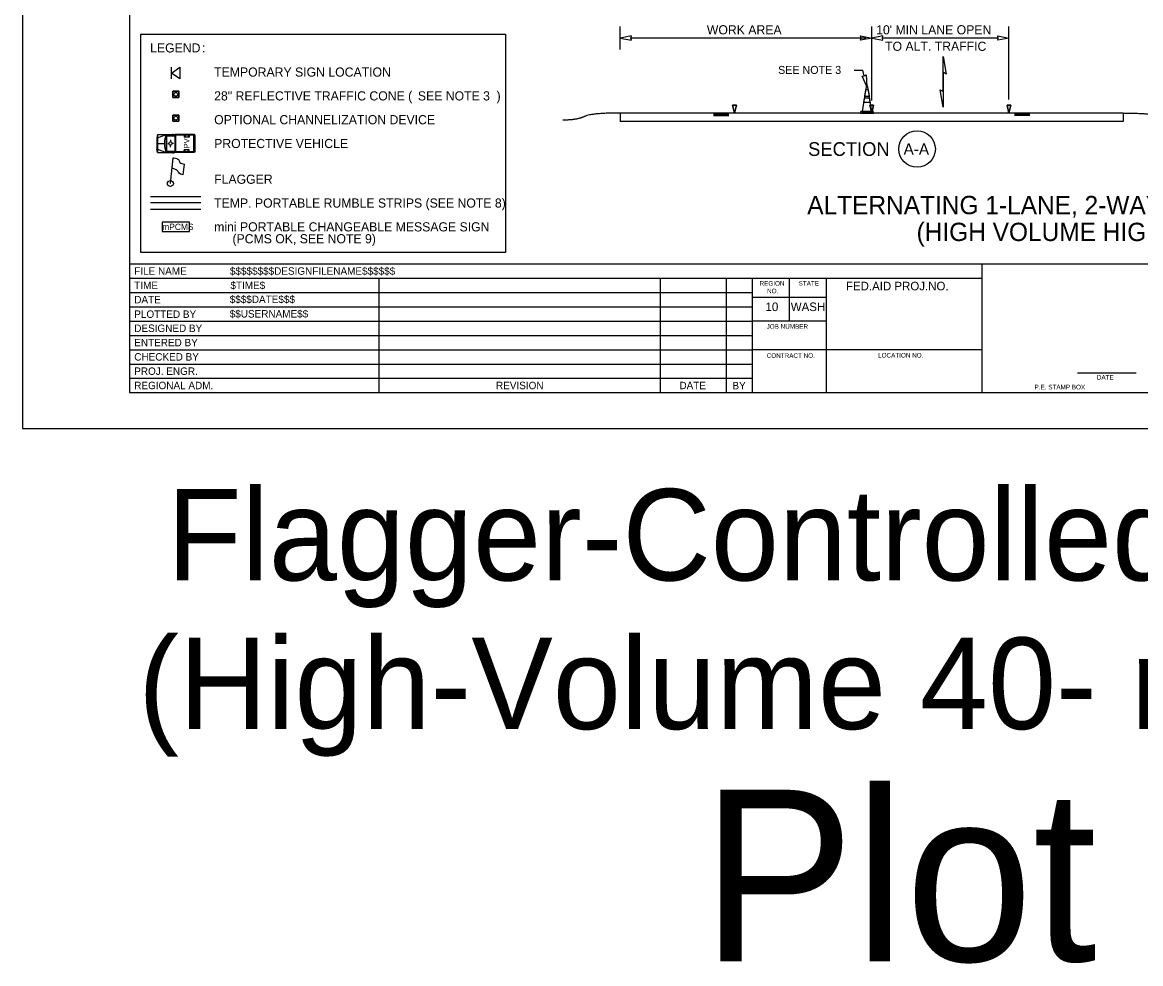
# Model space of a CAD drawing. Extents: x 99999.1 to 100095.7, y 99995 to 100010.7.
# Drawn here: x 100039.06 to 100048.84, y 99995.01 to 100003.24 of the extents above; entities that cross this region are included whole.
import ezdxf

# ---------------------------------------------------------------- set-up
doc = ezdxf.new("R2010")
doc.units = 0
for name, color, linetype in [('SH_DE_DetailHeading1Text', 7, 'Continuous'), ('SH_GI_PlotLimits', 7, 'Continuous'), ('SH_GI_SheetBorder', 7, 'Continuous'), ('SH_GI_SheetLocationText', 7, 'Continuous'), ('SH_GI_SheetTextInCells', 7, 'Continuous'), ('SH_GI_TitleBlockText', 7, 'Continuous'), ('TR_WZ_FlaggingStation', 7, 'Continuous'), ('TR_WZ_PCMS', 7, 'Continuous'), ('TR_WZ_PortableSignMountBlk-Org', 7, 'Continuous'), ('TR_WZ_ProtectiveVehicle', 7, 'Continuous'), ('TR_WZ_TrafficCone', 7, 'Continuous'), ('TR_WZ_TrafficConeElev', 7, 'Continuous'), ('TR_WZ_WorkZoneDetails', 7, 'Continuous'), ('TR_WZ_WorkZoneTextCurrent', 7, 'Continuous')]:
    doc.layers.add(name, color=color, linetype=linetype)

msp = doc.modelspace()

# ---------------------------------------------------------------- linework, layer by layer
at = {"layer": 'SH_GI_PlotLimits'}
msp.add_lwpolyline([(100039.0625, 99999.6875), (100056.0625, 99999.6875), (100056.0625, 100010.6875), (100039.0625, 100010.6875)], close=True, dxfattribs=at)
at = {"layer": 'SH_GI_SheetBorder'}
for p, q in [((100040, 100010.375), (100040, 100000)), ((100040, 100001.1259), (100055.75, 100001.1259)), ((100047.4566, 100000), (100047.4566, 100001.1259)), ((100040, 100001.0008), (100047.4566, 100001.0008)), ((100042.179, 100001.0008), (100042.179, 100000)), ((100044.641, 100001.0008), (100044.641, 100000)), ((100045.2164, 100001.0008), (100045.2164, 100000)), ((100045.4451, 100001.0008), (100045.4451, 100000)), ((100045.7719, 100000.6255), (100045.7719, 100001.0008)), ((100046.0956, 100000), (100046.0956, 100001.0008)), ((100040, 100000.8757), (100042.1821, 100000.8757)), ((100042.1821, 100000.8757), (100045.4466, 100000.8757)), ((100046.0958, 100000.831), (100045.4466, 100000.831)), ((100040, 100000.7506), (100042.1821, 100000.7506)), ((100042.1821, 100000.7506), (100045.4466, 100000.7506)), ((100040, 100000.6255), (100045.4466, 100000.6255)), ((100046.0958, 100000.6255), (100045.4466, 100000.6255)), ((100040, 100000.5004), (100045.4466, 100000.5004)), ((100040, 100000.3753), (100045.4466, 100000.3753)), ((100047.4566, 100000.3753), (100045.4466, 100000.3753)), ((100040, 100000.2502), (100045.4466, 100000.2502)), ((100040, 100000.1251), (100045.4466, 100000.1251)), ((100048.2903, 100000.1733), (100048.802, 100000.1733)), ((100040, 100000), (100055.75, 100000))]:
    msp.add_line(p, q, dxfattribs=at)
at = {"layer": 'TR_WZ_FlaggingStation'}
for p, q in [((100040.3571, 100001.8286), (100040.3828, 100002.0533)), ((100040.3723, 100001.9621), (100040.3828, 100002.0536)), ((100040.3723, 100001.9621), (100040.3723, 100001.9621)), ((100040.4771, 100001.9993), (100040.4665, 100001.9056))]:
    msp.add_line(p, q, dxfattribs=at)
for points in [[(100040.3828, 100002.0536), (100040.3874, 100002.0525), (100040.4016, 100002.0498), (100040.4127, 100002.0465), (100040.4204, 100002.0416), (100040.4273, 100002.0378), (100040.4318, 100002.0324), (100040.4352, 100002.0261), (100040.4356, 100002.0211), (100040.4399, 100002.0138), (100040.4486, 100002.0078), (100040.4585, 100002.0036), (100040.4771, 100001.9993)], [(100040.4665, 100001.9056), (100040.46, 100001.9067), (100040.4458, 100001.9104), (100040.4333, 100001.9188), (100040.4281, 100001.9273), (100040.425, 100001.9355), (100040.4177, 100001.9442), (100040.4089, 100001.9492), (100040.395, 100001.9548), (100040.3723, 100001.9621)]]:
    msp.add_lwpolyline(points, dxfattribs=at)
msp.add_circle((100040.3571, 100001.8286), 0.026, dxfattribs=at)
at = {"layer": 'TR_WZ_PCMS'}
msp.add_lwpolyline([(100040.2841, 100001.41), (100040.5241, 100001.41), (100040.5241, 100001.49), (100040.2841, 100001.49)], close=True, dxfattribs=at)
msp.add_lwpolyline([(100040.2841, 100001.41), (100040.5241, 100001.41), (100040.5241, 100001.49), (100040.2841, 100001.49), (100040.2841, 100001.41)], dxfattribs=at)
at = {"layer": 'TR_WZ_PortableSignMountBlk-Org'}
msp.add_line((100040.3682, 100002.7454), (100040.3682, 100002.8454), dxfattribs=at)
msp.add_lwpolyline([(100040.3682, 100002.7953), (100040.44, 100002.8454), (100040.44, 100002.7454)], close=True, dxfattribs=at)
at = {"layer": 'TR_WZ_ProtectiveVehicle'}
for p, q in [((100040.245, 100002.259), (100040.2376, 100002.2267)), ((100040.245, 100002.259), (100040.245, 100002.099)), ((100040.245, 100002.259), (100040.3962, 100002.259)), ((100040.245, 100002.2297), (100040.3206, 100002.259)), ((100040.3206, 100002.259), (100040.3206, 100002.099)), ((100040.322, 100002.259), (100040.322, 100002.099)), ((100040.322, 100002.259), (100040.3316, 100002.2466)), ((100040.322, 100002.2466), (100040.3962, 100002.2466)), ((100040.3756, 100002.2613), (100040.3846, 100002.2613)), ((100040.3962, 100002.259), (100040.3962, 100002.099)), ((100040.5629, 100002.259), (100040.3984, 100002.259)), ((100040.3984, 100002.259), (100040.3984, 100002.099)), ((100040.5583, 100002.2526), (100040.403, 100002.2526)), ((100040.403, 100002.2526), (100040.403, 100002.1054)), ((100040.4772, 100002.2526), (100040.4772, 100002.2342)), ((100040.4852, 100002.2526), (100040.4852, 100002.2342)), ((100040.5124, 100002.2526), (100040.5124, 100002.2342)), ((100040.5212, 100002.2526), (100040.5212, 100002.2342)), ((100040.5583, 100002.2526), (100040.5583, 100002.1054)), ((100040.5629, 100002.259), (100040.5629, 100002.099)), ((100040.5671, 100002.2564), (100040.5635, 100002.2564)), ((100040.5635, 100002.2564), (100040.5635, 100002.1017)), ((100040.5706, 100002.2515), (100040.5706, 100002.1065)), ((100040.2376, 100002.2267), (100040.2376, 100002.1313)), ((100040.245, 100002.179), (100040.3058, 100002.179)), ((100040.3341, 100002.1791), (100040.3442, 100002.1791)), ((100040.3582, 100002.2107), (100040.3582, 100002.1978)), ((100040.3588, 100002.1482), (100040.3586, 100002.1603)), ((100040.3695, 100002.1787), (100040.3695, 100002.1787)), ((100040.3829, 100002.1784), (100040.371, 100002.1787)), ((100040.5212, 100002.2342), (100040.4772, 100002.2342)), ((100040.5706, 100002.1903), (100040.5635, 100002.1873)), ((100040.5706, 100002.1678), (100040.5635, 100002.1708)), ((100040.5687, 100002.179), (100040.5654, 100002.179)), ((100040.5671, 100002.1813), (100040.5671, 100002.1768)), ((100040.245, 100002.099), (100040.2376, 100002.1313)), ((100040.245, 100002.1283), (100040.3206, 100002.099)), ((100040.245, 100002.099), (100040.3962, 100002.099)), ((100040.322, 100002.1114), (100040.3962, 100002.1114)), ((100040.3299, 100002.1114), (100040.322, 100002.099)), ((100040.3756, 100002.0968), (100040.3846, 100002.0968)), ((100040.5629, 100002.099), (100040.3984, 100002.099)), ((100040.5583, 100002.1054), (100040.403, 100002.1054)), ((100040.4772, 100002.1054), (100040.4772, 100002.1238)), ((100040.5212, 100002.1238), (100040.4772, 100002.1238)), ((100040.4852, 100002.1054), (100040.4852, 100002.1238)), ((100040.5124, 100002.1054), (100040.5124, 100002.1238)), ((100040.5212, 100002.1054), (100040.5212, 100002.1238)), ((100040.5671, 100002.1017), (100040.5635, 100002.1017))]:
    msp.add_line(p, q, dxfattribs=at)
for centre, major_axis, start_param, end_param in [((100040.4286, 100002.179), (0, -0.1679), 4.215667, 5.208926), ((100040.5671, 100002.2515), (0, 0.00488), 4.712389, 6.283185), ((100040.5671, 100002.1065), (0, -0.00488), 0, 1.570796)]:
    msp.add_ellipse(centre, major_axis=major_axis, ratio=0.73155, start_param=start_param, end_param=end_param, dxfattribs=at)
for centre, major_axis in [((100040.3582, 100002.179), (0, 0.0154)), ((100040.5671, 100002.179), (0, 0.00225))]:
    msp.add_ellipse(centre, major_axis=major_axis, ratio=0.73155, dxfattribs=at)
at = {"layer": 'TR_WZ_TrafficCone'}
for points in [[(100040.3775, 100002.6355), (100040.4308, 100002.6355), (100040.4308, 100002.5821), (100040.3775, 100002.5821), (100040.3775, 100002.6355)], [(100040.3775, 100002.5821), (100040.4308, 100002.5821), (100040.4308, 100002.6355), (100040.3775, 100002.6355), (100040.3775, 100002.5821)], [(100040.3775, 100002.4272), (100040.4308, 100002.4272), (100040.4308, 100002.3739), (100040.3775, 100002.3739), (100040.3775, 100002.4272)], [(100040.3775, 100002.3739), (100040.4308, 100002.3739), (100040.4308, 100002.4272), (100040.3775, 100002.4272), (100040.3775, 100002.3739)]]:
    msp.add_lwpolyline(points, dxfattribs=at)
for centre in [(100040.4041, 100002.6088), (100040.4041, 100002.4005)]:
    msp.add_circle(centre, 0.0167, dxfattribs=at)
at = {"layer": 'TR_WZ_TrafficConeElev'}
for p, q in [((100046.4363, 100002.6476), (100046.428, 100002.5934)), ((100046.4616, 100002.6476), (100046.4363, 100002.6476)), ((100046.4699, 100002.5934), (100046.4616, 100002.6476)), ((100046.4255, 100002.5768), (100046.4197, 100002.5393)), ((100046.4197, 100002.5393), (100046.4782, 100002.5393)), ((100046.4724, 100002.5768), (100046.4255, 100002.5768)), ((100046.428, 100002.5934), (100046.4699, 100002.5934)), ((100046.4782, 100002.5393), (100046.4724, 100002.5768)), ((100046.3953, 100002.458), (100046.3911, 100002.4538)), ((100046.3911, 100002.4538), (100046.3911, 100002.4455)), ((100046.3911, 100002.4455), (100046.5068, 100002.4455)), ((100046.4073, 100002.458), (100046.3953, 100002.458)), ((100046.5068, 100002.4538), (100046.5026, 100002.458)), ((100046.5068, 100002.4455), (100046.5068, 100002.4538))]:
    msp.add_line(p, q, dxfattribs=at)
msp.add_lwpolyline([(100046.4073, 100002.458), (100046.4906, 100002.458), (100046.4568, 100002.6788), (100046.4411, 100002.6788)], close=True, dxfattribs=at)
msp.add_lwpolyline([(100046.4073, 100002.458), (100046.4906, 100002.458), (100046.4568, 100002.6788), (100046.4411, 100002.6788)], close=True, dxfattribs=at)
msp.add_lwpolyline([(100046.5026, 100002.458), (100046.4906, 100002.458), (100046.4073, 100002.458)], dxfattribs=at)
at = {"layer": 'TR_WZ_WorkZoneDetails'}
for p, q in [((100044.2907, 100003.0015), (100044.2907, 100003.2015)), ((100046.4907, 100002.5552), (100046.4907, 100003.2015)), ((100047.6907, 100002.5652), (100047.6907, 100003.2015)), ((100046.4387, 100003.1015), (100044.3844, 100003.1015)), ((100047.597, 100003.1015), (100046.5844, 100003.1015)), ((100046.3358, 100002.8215), (100046.412, 100002.8215)), ((100046.4255, 100002.7696), (100046.412, 100002.8215)), ((100047.1157, 100002.8019), (100047.1157, 100002.6331)), ((100047.1157, 100002.6331), (100047.1157, 100002.8019)), ((100044.2907, 100002.4454), (100044.2907, 100002.3704)), ((100048.6907, 100002.4454), (100044.2907, 100002.4454)), ((100045.1077, 100002.4402), (100045.2407, 100002.4402)), ((100047.8737, 100002.4398), (100047.7407, 100002.4398)), ((100048.6907, 100002.4454), (100048.6907, 100002.3704)), ((100048.6907, 100002.3704), (100044.2907, 100002.3704)), ((100045.1077, 100002.4346), (100045.2407, 100002.4346)), ((100045.1077, 100002.4289), (100045.2407, 100002.4289)), ((100045.1077, 100002.4237), (100045.2407, 100002.4237)), ((100047.8737, 100002.4342), (100047.7407, 100002.4342)), ((100047.8737, 100002.4285), (100047.7407, 100002.4285)), ((100047.8737, 100002.4233), (100047.7407, 100002.4233)), ((100040.6241, 100001.7135), (100040.1841, 100001.7135)), ((100040.6241, 100001.6587), (100040.1841, 100001.6587)), ((100040.6241, 100001.603), (100040.1841, 100001.603))]:
    msp.add_line(p, q, dxfattribs=at)
for points in [[(100044.2907, 100003.1015), (100044.389, 100003.0822), (100044.3844, 100003.1015), (100044.389, 100003.1208)], [(100046.4907, 100003.1015), (100046.3924, 100003.0822), (100046.397, 100003.1015), (100046.3924, 100003.1208)], [(100046.4907, 100003.1015), (100046.589, 100003.0822), (100046.5844, 100003.1015), (100046.589, 100003.1208)], [(100047.6907, 100003.1015), (100047.5924, 100003.0822), (100047.597, 100003.1015), (100047.5924, 100003.1208)], [(100047.1157, 100002.9395), (100047.1427, 100002.7863), (100047.1157, 100002.8019)], [(100046.449, 100002.6788), (100046.4057, 100002.7692), (100046.4255, 100002.7696), (100046.443, 100002.7788)], [(100047.1157, 100002.4954), (100047.0887, 100002.6487), (100047.1157, 100002.6331)], [(100045.2907, 100002.4454), (100045.274, 100002.5152), (100045.3073, 100002.5152)], [(100046.4907, 100002.4454), (100046.474, 100002.5152), (100046.5074, 100002.5152)], [(100047.6907, 100002.4454), (100047.674, 100002.5152), (100047.7073, 100002.5152)]]:
    msp.add_lwpolyline(points, close=True, dxfattribs=at)
for points in [[(100045.3073, 100002.5152), (100045.274, 100002.5152), (100045.2907, 100002.4454), (100045.3073, 100002.5152)], [(100046.5074, 100002.5152), (100046.474, 100002.5152), (100046.4907, 100002.4454), (100046.5074, 100002.5152)], [(100047.7073, 100002.5152), (100047.674, 100002.5152), (100047.6907, 100002.4454), (100047.7073, 100002.5152)]]:
    msp.add_lwpolyline(points, dxfattribs=at)
msp.add_circle((100046.8872, 100002.1305), 0.16, dxfattribs=at)
for points in [[(100044.2907, 100002.4454), (100044.0395, 100002.4454), (100043.914, 100002.3833), (100043.7886, 100002.3833)], [(100048.6907, 100002.4454), (100048.9419, 100002.4456), (100049.0674, 100002.3835), (100049.1928, 100002.3836)]]:
    msp.add_open_spline(points, degree=2, dxfattribs=at)
at = {"layer": 'TR_WZ_WorkZoneTextCurrent'}
msp.add_lwpolyline([(100040.1, 100003.1351), (100043.2886, 100003.1351), (100043.2886, 100001.2259), (100040.1, 100001.2259)], close=True, dxfattribs=at)

# ---------------------------------------------------------------- texts
at = {"layer": 'SH_DE_DetailHeading1Text'}
for s, p in [('ALTERNATING 1-LANE, 2-WAY TRAFFIC: FLAGGER-CONTROLLED', (100045.9266, 100001.5606)), ('(HIGH VOLUME HIGHWAYS, 40 MPH OR LESS)', (100046.8827, 100001.3259))]:
    msp.add_text(s, height=0.16, rotation=360, dxfattribs=at).set_placement(p)
at = {"layer": 'SH_GI_SheetLocationText'}
for s, height, p in [('Flagger-Controlled Alt Traffic+RS', 0.8, (100040.3275, 99998.3571)), ('(High-Volume 40- mph Highways)', 0.8, (100040.0757, 99997.0571)), ('Plot 3', 1.5, (100045.0008, 99995.0267))]:
    msp.add_text(s, height=height, dxfattribs=at).set_placement(p)
at = {"layer": 'SH_GI_SheetTextInCells'}
for s, height, p in [('FILE NAME', 0.06505, (100040.041, 100001.0308)), ('TIME', 0.06505, (100040.041, 100000.9057)), ('REGION', 0.04003, (100045.5099, 100000.9352)), ('STATE', 0.04003, (100045.8511, 100000.9357)), ('FED.AID PROJ.NO.', 0.07506, (100046.2652, 100000.8945)), ('NO.', 0.04003, (100045.5752, 100000.869)), ('DATE', 0.06505, (100040.041, 100000.7806)), ('10', 0.07506, (100045.5621, 100000.7131)), ('WASH', 0.07506, (100045.7826, 100000.7131)), ('PLOTTED BY', 0.06505, (100040.041, 100000.6538)), ('DESIGNED BY', 0.065052, (100040.041, 100000.5304)), ('JOB NUMBER', 0.04003, (100045.5712, 100000.5587)), ('ENTERED BY', 0.06505, (100040.041, 100000.4053)), ('CHECKED BY', 0.06505, (100040.041, 100000.2802)), ('CONTRACT NO.', 0.040032, (100045.5725, 100000.3037)), ('LOCATION NO.', 0.040032, (100046.5465, 100000.3067)), ('PROJ. ENGR.', 0.065052, (100040.041, 100000.1551)), ('REGIONAL ADM.', 0.065052, (100040.041, 100000.03)), ('REVISION', 0.06505, (100043.2048, 100000.03)), ('DATE', 0.06505, (100044.8091, 100000.03)), ('BY', 0.06505, (100045.2725, 100000.0285)), ('DATE', 0.04003, (100048.4597, 100000.1141)), ('P.E. STAMP BOX', 0.040032, (100047.915, 100000.0286))]:
    msp.add_text(s, height=height, dxfattribs=at).set_placement(p)
at = {"layer": 'SH_GI_TitleBlockText'}
for s, height, p in [('$$$$$$$$DESIGNFILENAME$$$$$$', 0.065052, (100040.8775, 100001.0308)), ('$TIME$', 0.06505, (100040.882, 100000.9059)), ('$$$$DATE$$$', 0.065052, (100040.8759, 100000.7835)), ('$$USERNAME$$', 0.065052, (100040.8759, 100000.6567))]:
    msp.add_text(s, height=height, dxfattribs=at).set_placement(p)
at = {"layer": 'TR_WZ_PCMS'}
msp.add_text('mPCMS', height=0.055, rotation=360, dxfattribs=at).set_placement((100040.2856, 100001.4225))
at = {"layer": 'TR_WZ_ProtectiveVehicle'}
msp.add_text('PV', height=0.048, rotation=90, dxfattribs=at).set_placement((100040.5232, 100002.136))
at = {"layer": 'TR_WZ_WorkZoneDetails'}
for s, p in [('WORK AREA', (100045.0487, 100003.1335)), ("10' MIN LANE OPEN", (100046.5294, 100003.1335)), ('TO ALT. TRAFFIC', (100046.6075, 100002.9895))]:
    msp.add_text(s, height=0.08, dxfattribs=at).set_placement(p)
for s, height, p in [('SECTION', 0.12, (100045.9342, 100002.0705)), ('A-A', 0.1, (100046.7694, 100002.0805))]:
    msp.add_text(s, height=height, rotation=360, dxfattribs=at).set_placement(p)
at = {"layer": 'TR_WZ_WorkZoneTextCurrent'}
for s, p in [('LEGEND', (100040.18, 100002.9751)), (':', (100040.6328, 100002.9751)), ('TEMPORARY SIGN LOCATION ', (100040.74, 100002.7639)), ('28" REFLECTIVE TRAFFIC CONE (', (100040.74, 100002.5556)), ('SEE NOTE 3', (100042.5216, 100002.5556)), (')', (100043.2099, 100002.5556)), ('OPTIONAL CHANNELIZATION DEVICE', (100040.74, 100002.3473)), ('PROTECTIVE VEHICLE', (100040.74, 100002.139)), ('FLAGGER', (100040.74, 100001.8266)), ('TEMP. PORTABLE RUMBLE STRIPS (SEE NOTE 8)', (100040.74, 100001.6183)), ('mini PORTABLE CHANGEABLE MESSAGE SIGN', (100040.74, 100001.41)), ('(PCMS OK, SEE NOTE 9)', (100040.9, 100001.3059))]:
    msp.add_text(s, height=0.08, rotation=360, dxfattribs=at).set_placement(p)
msp.add_text('SEE NOTE 3', height=0.07, dxfattribs=at).set_placement((100045.672, 100002.7875))

doc.saveas('drawing.dxf')
